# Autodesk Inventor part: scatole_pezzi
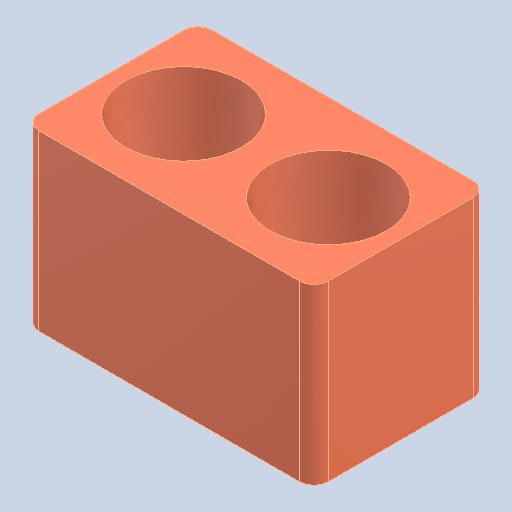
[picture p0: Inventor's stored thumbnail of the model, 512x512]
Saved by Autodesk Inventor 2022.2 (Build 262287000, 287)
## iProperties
Created: 2024-10
Part Number: scatole_pezzi
Material: Generico
Document SubType Name: Modeling
Designer: 18907419
Density: 1 g/cm^3
Appearance: Default
Author: 18907419
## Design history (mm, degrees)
feature "Solido1"
node "Solido2"
